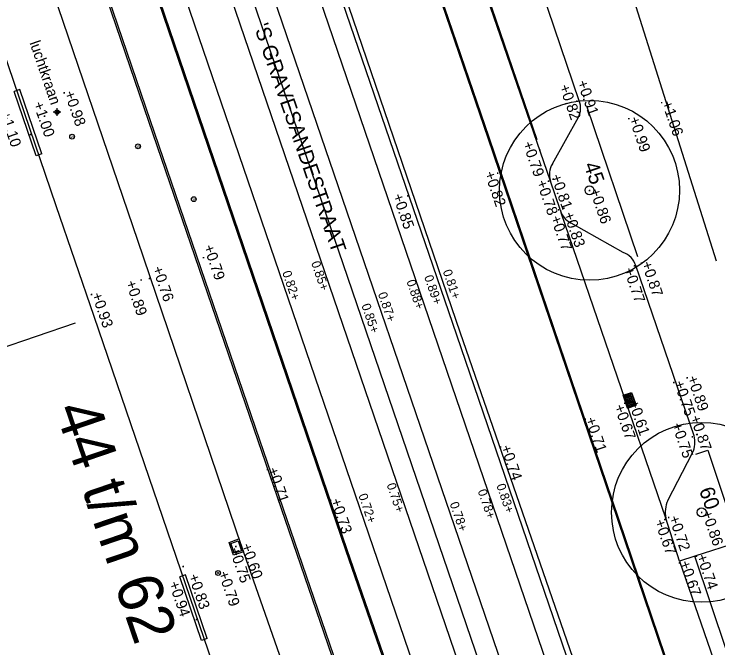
# Model space of a CAD drawing. Extents: x 122462 to 123306, y 485548 to 486417.
# Drawn here: x 122852.27 to 122875.74, y 486006.21 to 486027.34 of the extents above; entities that cross this region are included whole.
import ezdxf

# ---------------------------------------------------------------- set-up
doc = ezdxf.new("R2010")
doc.units = 0
for name, color, linetype in [('B-WE-GR-BOOM-S', 7, 'Continuous'), ('B-WE-GR-BOOM_BOOMDIAMETER-T25', 7, 'Continuous'), ('B-WE-IE-MEUBILAIR_WEGMEUBILAIR-S', 7, 'Continuous'), ('B-WE-OG-BEBOUWING_ROOSTER-G', 7, 'Continuous'), ('B-WE-OG-HOOGTEPUNT-S', 7, 'Continuous'), ('B-WE-OG-PASPUNT_ALGEMEEN-S', 7, 'Continuous'), ('B-WE-OG-TOPOGRAFIE_STRAATNAAM', 7, 'Continuous'), ('B-WE-OG-TOPOKAART-G', 7, 'Continuous'), ('B-WE-RI-HWA_KOLK-S', 7, 'Continuous'), ('B-WE-VH-KANTOPSLUITING_ELEMENT_INRIT-G', 7, 'Continuous'), ('B-WE-VH-KANTOPSLUITING_OPSLUITBAND_100X200-G', 7, 'Continuous'), ('B-WE-VH-KANTOPSLUITING_TROTTOIRBAND_130 150-G', 7, 'Continuous'), ('B-WE-VH-MATERIAALGRENS_ASFALT-G', 7, 'Continuous'), ('B-WE-VW-MARKERING_LANGS_STREEP_11_010-G', 7, 'Continuous'), ('B-WE-ZZ-T18', 7, 'Continuous'), ('Bestaand Hoogtemaat vast', 7, 'Continuous'), ('Level 22', 7, 'Continuous'), ('Level 4', 7, 'Continuous'), ('Level 58', 7, 'Continuous'), ('V markering 1-1 10 cm', 7, 'Continuous'), ('V markering ononderbroken streep 10 cm', 7, 'Continuous'), ('V materiaalscheiding algemeen', 7, 'Continuous'), ('V Rails', 7, 'Continuous'), ('V riool trottoirkolk', 7, 'Continuous'), ('V RWS-band 115-225x250 mm specie', 7, 'Continuous'), ('V trottoirband 180-200x250 mm specie', 7, 'Continuous')]:
    doc.layers.add(name, color=color, linetype=linetype)

msp = doc.modelspace()

# ---------------------------------------------------------------- linework, layer by layer
at = {"layer": 'B-WE-GR-BOOM-S'}
for centre, radius in [((122871.456, 486021.467), 3), ((122871.456, 486021.467), 0.15), ((122871.456, 486021.467), 0.15), ((122875.191, 486010.727), 3), ((122875.191, 486010.727), 0.15), ((122875.191, 486010.727), 0.15)]:
    msp.add_circle(centre, radius, dxfattribs=at)
at = {"layer": 'B-WE-IE-MEUBILAIR_WEGMEUBILAIR-S'}
for centre in [(122854.207, 486023.256), (122856.406, 486022.933), (122858.264, 486021.172), (122859.075, 486008.705)]:
    msp.add_circle(centre, 0.08, dxfattribs=at)
at = {"layer": 'B-WE-OG-BEBOUWING_ROOSTER-G'}
for p, q in [((122852.466, 486024.824), (122852.277, 486024.759)), ((122853.195, 486022.687), (122852.466, 486024.824)), ((122853.006, 486022.622), (122852.277, 486024.759)), ((122853.195, 486022.687), (122853.006, 486022.622)), ((122857.991, 486008.642), (122857.802, 486008.578)), ((122858.715, 486006.52), (122857.991, 486008.642)), ((122858.526, 486006.456), (122857.802, 486008.578)), ((122858.715, 486006.52), (122858.526, 486006.456))]:
    msp.add_line(p, q, dxfattribs=at)
at = {"layer": 'B-WE-OG-HOOGTEPUNT-S'}
for p, q in [((122853.922, 486024.719), (122853.962, 486024.719)), ((122853.942, 486024.739), (122853.942, 486024.699)), ((122871.249, 486024.593), (122871.289, 486024.593)), ((122871.269, 486024.613), (122871.269, 486024.573)), ((122871.009, 486024.437), (122871.049, 486024.437)), ((122871.029, 486024.457), (122871.029, 486024.417)), ((122873.841, 486024.39), (122873.881, 486024.39)), ((122873.861, 486024.41), (122873.861, 486024.37)), ((122853.267, 486023.941), (122853.307, 486023.941)), ((122853.287, 486023.961), (122853.287, 486023.921)), ((122872.765, 486023.878), (122872.765, 486023.838)), ((122872.745, 486023.858), (122872.785, 486023.858)), ((122852.804, 486023.328), (122852.844, 486023.328)), ((122852.824, 486023.348), (122852.824, 486023.308)), ((122869.783, 486022.807), (122869.823, 486022.807)), ((122869.803, 486022.827), (122869.803, 486022.787)), ((122868.374, 486022.038), (122868.414, 486022.038)), ((122868.394, 486022.058), (122868.394, 486022.018)), ((122870.072, 486021.777), (122870.112, 486021.777)), ((122870.092, 486021.797), (122870.092, 486021.757)), ((122870.22, 486021.843), (122870.26, 486021.843)), ((122870.24, 486021.863), (122870.24, 486021.823)), ((122865.381, 486021.288), (122865.421, 486021.288)), ((122865.401, 486021.308), (122865.401, 486021.268)), ((122871.438, 486021.464), (122871.478, 486021.464)), ((122871.458, 486021.484), (122871.458, 486021.444)), ((122870.428, 486020.833), (122870.428, 486020.793)), ((122870.581, 486020.872), (122870.621, 486020.872)), ((122870.601, 486020.892), (122870.601, 486020.852)), ((122870.408, 486020.813), (122870.448, 486020.813)), ((122858.564, 486019.221), (122858.604, 486019.221)), ((122858.584, 486019.241), (122858.584, 486019.201)), ((122872.933, 486018.951), (122872.973, 486018.951)), ((122872.953, 486018.971), (122872.953, 486018.931)), ((122873.163, 486019.035), (122873.203, 486019.035)), ((122873.183, 486019.055), (122873.183, 486019.015)), ((122856.486, 486018.476), (122856.526, 486018.476)), ((122856.506, 486018.496), (122856.506, 486018.456)), ((122856.763, 486018.523), (122856.803, 486018.523)), ((122856.783, 486018.543), (122856.783, 486018.503)), ((122854.853, 486018.015), (122854.853, 486017.975)), ((122854.833, 486017.995), (122854.873, 486017.995)), ((122874.688, 486015.217), (122874.728, 486015.217)), ((122874.708, 486015.237), (122874.708, 486015.197)), ((122874.243, 486015.055), (122874.283, 486015.055)), ((122874.263, 486015.075), (122874.263, 486015.035)), ((122872.793, 486014.486), (122872.793, 486014.446)), ((122872.61, 486014.365), (122872.65, 486014.365)), ((122872.63, 486014.385), (122872.63, 486014.345)), ((122872.773, 486014.466), (122872.813, 486014.466)), ((122871.293, 486013.838), (122871.333, 486013.838)), ((122871.313, 486013.858), (122871.313, 486013.818)), ((122875.026, 486013.325), (122875.066, 486013.325)), ((122875.046, 486013.345), (122875.046, 486013.305)), ((122874.864, 486013.242), (122874.904, 486013.242)), ((122874.884, 486013.262), (122874.884, 486013.222)), ((122868.469, 486012.908), (122868.509, 486012.908)), ((122868.489, 486012.928), (122868.489, 486012.888)), ((122860.697, 486012.16), (122860.737, 486012.16)), ((122860.717, 486012.18), (122860.717, 486012.14)), ((122862.801, 486011.129), (122862.841, 486011.129)), ((122862.821, 486011.149), (122862.821, 486011.109)), ((122875.193, 486010.744), (122875.193, 486010.704)), ((122873.969, 486010.505), (122873.969, 486010.465)), ((122874.073, 486010.555), (122874.113, 486010.555)), ((122874.093, 486010.575), (122874.093, 486010.535)), ((122875.173, 486010.724), (122875.213, 486010.724)), ((122873.949, 486010.485), (122873.989, 486010.485)), ((122859.641, 486009.589), (122859.681, 486009.589)), ((122859.661, 486009.609), (122859.661, 486009.569)), ((122859.821, 486009.625), (122859.861, 486009.625)), ((122859.841, 486009.645), (122859.841, 486009.605)), ((122874.998, 486009.27), (122875.038, 486009.27)), ((122875.018, 486009.29), (122875.018, 486009.25)), ((122857.886, 486008.919), (122857.926, 486008.919)), ((122857.906, 486008.939), (122857.906, 486008.899)), ((122874.436, 486009.048), (122874.476, 486009.048)), ((122874.456, 486009.068), (122874.456, 486009.028)), ((122859.055, 486008.705), (122859.095, 486008.705)), ((122859.075, 486008.725), (122859.075, 486008.685)), ((122858.336, 486007.154), (122858.376, 486007.154)), ((122858.356, 486007.174), (122858.356, 486007.134))]:
    msp.add_line(p, q, dxfattribs=at)
at = {"layer": 'B-WE-OG-PASPUNT_ALGEMEEN-S'}
for p, q in [((122853.708, 486024.076), (122853.708, 486024.204)), ((122853.708, 486024.076), (122853.58, 486024.076)), ((122853.708, 486023.948), (122853.708, 486024.076)), ((122853.836, 486024.076), (122853.708, 486024.076))]:
    msp.add_line(p, q, dxfattribs=at)
for radius in [0.0731, 0.033]:
    msp.add_circle((122853.708, 486024.076), radius, dxfattribs=at)
at = {"layer": 'B-WE-OG-TOPOKAART-G'}
msp.add_line((122860.981, 485999.574), (122854.941, 486017.262), dxfattribs=at)
msp.add_lwpolyline([(122854.941, 486017.262), (122853.681, 486020.951), (122848.906, 486034.937)], dxfattribs=at)
at = {"layer": 'B-WE-RI-HWA_KOLK-S'}
for p, q in [((122872.577, 486014.63), (122872.861, 486014.727)), ((122872.861, 486014.727), (122873.007, 486014.301)), ((122872.723, 486014.204), (122872.577, 486014.63)), ((122872.596, 486014.621), (122872.852, 486014.708)), ((122872.732, 486014.223), (122872.596, 486014.621)), ((122872.852, 486014.708), (122872.988, 486014.311)), ((122872.723, 486014.204), (122873.007, 486014.301)), ((122872.732, 486014.223), (122872.988, 486014.311))]:
    msp.add_line(p, q, dxfattribs=at)
for points in [[(122872.637, 486014.604), (122872.641, 486014.592)], [(122872.817, 486014.676), (122872.643, 486014.617)], [(122872.653, 486014.586), (122872.828, 486014.646)], [(122872.653, 486014.556), (122872.657, 486014.545)], [(122872.834, 486014.629), (122872.659, 486014.569)], [(122872.669, 486014.509), (122872.673, 486014.498)], [(122872.67, 486014.539), (122872.844, 486014.599)], [(122872.85, 486014.582), (122872.676, 486014.522)], [(122872.686, 486014.492), (122872.86, 486014.551)], [(122872.866, 486014.534), (122872.692, 486014.475)], [(122872.702, 486014.444), (122872.876, 486014.504)], [(122872.882, 486014.487), (122872.708, 486014.427)], [(122872.834, 486014.659), (122872.83, 486014.67)], [(122872.85, 486014.611), (122872.846, 486014.623)], [(122872.866, 486014.564), (122872.863, 486014.575)], [(122872.883, 486014.517), (122872.879, 486014.528)], [(122872.899, 486014.469), (122872.895, 486014.481)], [(122872.685, 486014.462), (122872.689, 486014.451)], [(122872.702, 486014.415), (122872.706, 486014.403)], [(122872.718, 486014.397), (122872.893, 486014.457)], [(122872.718, 486014.367), (122872.722, 486014.356)], [(122872.898, 486014.44), (122872.724, 486014.38)], [(122872.734, 486014.35), (122872.909, 486014.409)], [(122872.734, 486014.32), (122872.738, 486014.309)], [(122872.915, 486014.392), (122872.74, 486014.333)], [(122872.75, 486014.273), (122872.754, 486014.261)], [(122872.751, 486014.302), (122872.925, 486014.362)], [(122872.931, 486014.345), (122872.757, 486014.285)], [(122872.767, 486014.255), (122872.941, 486014.315)], [(122872.915, 486014.422), (122872.911, 486014.433)], [(122872.931, 486014.375), (122872.927, 486014.386)], [(122872.947, 486014.327), (122872.944, 486014.339)]]:
    msp.add_lwpolyline(points, dxfattribs=at)
for centre, start, end in [((122872.646, 486014.607), 108.9043, 198.9043), ((122872.65, 486014.596), 198.9043, 288.9043), ((122872.663, 486014.56), 108.9043, 198.9043), ((122872.666, 486014.548), 198.9043, 288.9043), ((122872.679, 486014.512), 108.9043, 198.9043), ((122872.683, 486014.501), 198.9043, 288.9043), ((122872.821, 486014.667), 18.9043, 108.9043), ((122872.825, 486014.655), 288.9043, 18.9043), ((122872.837, 486014.619), 18.9043, 108.9043), ((122872.841, 486014.608), 288.9043, 18.9043), ((122872.853, 486014.572), 18.9043, 108.9043), ((122872.857, 486014.561), 288.9043, 18.9043), ((122872.869, 486014.525), 18.9043, 108.9043), ((122872.873, 486014.513), 288.9043, 18.9043), ((122872.885, 486014.478), 18.9043, 108.9043), ((122872.695, 486014.465), 108.9043, 198.9043), ((122872.699, 486014.454), 198.9043, 288.9043), ((122872.711, 486014.418), 108.9043, 198.9043), ((122872.715, 486014.406), 198.9043, 288.9043), ((122872.727, 486014.37), 108.9043, 198.9043), ((122872.731, 486014.359), 198.9043, 288.9043), ((122872.744, 486014.323), 108.9043, 198.9043), ((122872.747, 486014.312), 198.9043, 288.9043), ((122872.76, 486014.276), 108.9043, 198.9043), ((122872.764, 486014.265), 198.9043, 288.9043), ((122872.889, 486014.466), 288.9043, 18.9043), ((122872.902, 486014.43), 18.9043, 108.9043), ((122872.906, 486014.419), 288.9043, 18.9043), ((122872.918, 486014.383), 18.9043, 108.9043), ((122872.922, 486014.372), 288.9043, 18.9043), ((122872.934, 486014.336), 18.9043, 108.9043), ((122872.938, 486014.324), 288.9043, 18.9043)]:
    msp.add_arc(centre, 0.01, start, end, dxfattribs=at)
at = {"layer": 'B-WE-VH-KANTOPSLUITING_ELEMENT_INRIT-G'}
msp.add_lwpolyline([(122876.1, 486004.342), (122876.567, 486004.501), (122874.962, 486009.263), (122874.461, 486009.099)], close=True, dxfattribs=at)
at = {"layer": 'B-WE-VH-KANTOPSLUITING_OPSLUITBAND_100X200-G'}
msp.add_line((122871.36, 486024.279), (122873.059, 486019.257), dxfattribs=at)
msp.add_lwpolyline([(122875.003, 486012.672), (122875.403, 486012.797), (122876.421, 486009.733), (122874.962, 486009.263)], dxfattribs=at)
at = {"layer": 'B-WE-VH-KANTOPSLUITING_TROTTOIRBAND_130 150-G'}
msp.add_line((122874.461, 486009.099), (122873.998, 486010.535), dxfattribs=at)
for points in [[(122871.112, 486024.447), (122869.664, 486028.716)], [(122870.22, 486022.347), (122871.085, 486023.901)], [(122870.474, 486020.826), (122870.152, 486021.777)], [(122872.577, 486019.394), (122870.84, 486020.375)], [(122874.942, 486013.282), (122872.999, 486018.955)], [(122874.062, 486011.124), (122874.892, 486012.707)]]:
    msp.add_lwpolyline(points, dxfattribs=at)
for centre, radius, start, end in [((122870.516, 486024.203), 0.644, 332.0526, 22.274), ((122870.788, 486021.99), 0.671, 147.8548, 198.5105), ((122871.137, 486020.99), 0.683, 193.9744, 244.2077), ((122872.362, 486018.764), 0.665, 16.6992, 71.1589), ((122874.079, 486013.068), 0.889, 336.0879, 13.9552), ((122875.015, 486010.722), 1.034, 157.1414, 190.4477)]:
    msp.add_arc(centre, radius, start, end, dxfattribs=at)
at = {"layer": 'B-WE-VH-MATERIAALGRENS_ASFALT-G'}
for p, q in [((122870.152, 486021.777), (122867.145, 486030.539)), ((122873.998, 486010.535), (122870.512, 486020.715))]:
    msp.add_line(p, q, dxfattribs=at)
at = {"layer": 'B-WE-VW-MARKERING_LANGS_STREEP_11_010-G'}
msp.add_lwpolyline([(122869.714, 486023.153), (122867.665, 486029.129)], dxfattribs=at)
at = {"layer": 'Level 22'}
msp.add_lwpolyline([(122868.721, 486040.257), (122871.2, 486033.479), (122872.44, 486029.379), (122872.864, 486028.033), (122875.673, 486019.114)], dxfattribs=at)
at = {"layer": 'Level 4'}
msp.add_line((122844.648, 486013.747), (122854.324, 486017.051), dxfattribs=at)
at = {"layer": 'V markering 1-1 10 cm'}
for points in [[(122861.268, 486043.255), (122864.477, 486033.82), (122868.105, 486023.234), (122872.215, 486011.133), (122877.675, 485994.999), (122880.312, 485987.313), (122885.038, 485973.513), (122892.674, 485951.631), (122899.173, 485932.732), (122905.905, 485913.305)], [(122897.69, 485909.552), (122896.019, 485914.579), (122892.466, 485924.842), (122886.539, 485941.858), (122880.87, 485958.414), (122875.603, 485973.852), (122873.11, 485981.1), (122869.222, 485992.577), (122863.38, 486009.478), (122855.336, 486033.09), (122853.219, 486039.33)], [(122869.601, 485986.295), (122864.164, 486002.161), (122860.412, 486013.116), (122856.761, 486023.765), (122852.874, 486035.171)]]:
    msp.add_lwpolyline(points, dxfattribs=at)
at = {"layer": 'V markering ononderbroken streep 10 cm'}
msp.add_line((122874.406, 485986.361), (122855.755, 486040.94), dxfattribs=at)
msp.add_lwpolyline([(122878.319, 485984.197), (122872.773, 486000.466), (122867.161, 486016.698), (122860.607, 486035.872), (122857.454, 486044.963)], dxfattribs=at)
at = {"layer": 'V materiaalscheiding algemeen'}
for points in [[(122897.072, 485911.4), (122895.975, 485914.564), (122892.423, 485924.827), (122886.495, 485941.843), (122880.827, 485958.399), (122875.559, 485973.837), (122873.066, 485981.085), (122869.178, 485992.562), (122863.337, 486009.463), (122855.292, 486033.075), (122851.509, 486044.226)], [(122861.232, 486043.247), (122864.442, 486033.808), (122868.07, 486023.222), (122872.18, 486011.121), (122877.64, 485994.987), (122880.277, 485987.301), (122885.003, 485973.501), (122892.639, 485951.618), (122899.138, 485932.72), (122905.87, 485913.293)], [(122869.833, 485985.807), (122864.223, 486002.181), (122860.47, 486013.137), (122856.82, 486023.786), (122852.933, 486035.191), (122852.304, 486036.83)]]:
    msp.add_lwpolyline(points, dxfattribs=at)
at = {"layer": 'V Rails'}
for p, q in [((122859.04, 486037.86), (122898.563, 485922.205)), ((122857.682, 486037.396), (122897.205, 485921.741)), ((122856.774, 486035.862), (122895.923, 485921.303)), ((122855.416, 486035.398), (122894.565, 485920.838))]:
    msp.add_line(p, q, dxfattribs=at)
at = {"layer": 'V riool trottoirkolk'}
for p, q in [((122859.44, 486009.723), (122859.77, 486009.838)), ((122859.77, 486009.838), (122859.919, 486009.413)), ((122859.787, 486009.791), (122859.782, 486009.789)), ((122859.588, 486009.298), (122859.44, 486009.723)), ((122859.776, 486009.777), (122859.791, 486009.732)), ((122859.791, 486009.732), (122859.802, 486009.701)), ((122859.82, 486009.697), (122859.815, 486009.695)), ((122859.817, 486009.659), (122859.843, 486009.583)), ((122859.828, 486009.673), (122859.823, 486009.671)), ((122859.861, 486009.579), (122859.856, 486009.577)), ((122859.869, 486009.555), (122859.864, 486009.553)), ((122859.919, 486009.413), (122859.588, 486009.298)), ((122859.858, 486009.541), (122859.885, 486009.465)), ((122859.902, 486009.461), (122859.897, 486009.459))]:
    msp.add_line(p, q, dxfattribs=at)
msp.add_lwpolyline([(122859.619, 486009.362), (122859.503, 486009.692), (122859.74, 486009.775), (122859.855, 486009.444)], close=True, dxfattribs=at)
for centre, start, end in [((122859.785, 486009.78), 109.2454, 199.2454), ((122859.812, 486009.704), 199.2454, 289.2454), ((122859.826, 486009.662), 109.2454, 199.2454), ((122859.853, 486009.586), 199.2454, 289.2454), ((122859.868, 486009.544), 109.2454, 199.2454), ((122859.894, 486009.468), 199.2454, 289.2454)]:
    msp.add_arc(centre, 0.01, start, end, dxfattribs=at)
at = {"layer": 'V RWS-band 115-225x250 mm specie'}
msp.add_lwpolyline([(122856.63, 486046.061), (122856.864, 486046.126), (122860.451, 486035.813), (122867.025, 486016.652), (122872.586, 486000.358), (122878.14, 485984.014)], dxfattribs=at)
at = {"layer": 'V trottoirband 180-200x250 mm specie'}
msp.add_lwpolyline([(122852.481, 486031.173), (122852.776, 486030.329), (122853.248, 486029.041), (122856.391, 486019.807), (122859.841, 486009.625), (122862.795, 486001.163), (122864.85, 485995.031), (122866.797, 485989.319), (122867.519, 485987.249)], dxfattribs=at)

# ---------------------------------------------------------------- texts
at = {"layer": 'B-WE-GR-BOOM_BOOMDIAMETER-T25'}
for s, rotation, p in [('45', 289, (122871.261, 486022.317)), ('60', 289.2634, (122875.102, 486011.471))]:
    msp.add_text(s, height=0.5, rotation=rotation, dxfattribs=at).set_placement(p)
at = {"layer": 'B-WE-IE-MEUBILAIR_WEGMEUBILAIR-S'}
for p in [(122854.165, 486023.214), (122856.364, 486022.891), (122858.221, 486021.13), (122859.033, 486008.663)]:
    msp.add_text('W', height=0.08, dxfattribs=at).set_placement(p)
at = {"layer": 'B-WE-OG-HOOGTEPUNT-S'}
for s, rotation, p in [('+0.91', 289.2634, (122871.038, 486025.071)), ('+0.82', 289.2634, (122870.442, 486024.928)), ('+0.98', 289, (122853.942, 486024.719)), ('+1.00', 289, (122852.907, 486024.358)), ('+1.06', 289, (122873.861, 486024.39)), ('+1.10', 289, (122851.792, 486024.027)), ('+0.99', 289, (122872.765, 486023.858)), ('+0.79', 289.2634, (122869.221, 486023.032)), ('+0.82', 289, (122867.947, 486022.038)), ('+0.78', 289.2634, (122869.679, 486021.745)), ('+0.81', 289.2634, (122870.162, 486021.937)), ('+0.85', 289, (122864.889, 486021.288)), ('+0.86', 289, (122871.458, 486021.464)), ('+0.77', 289.2634, (122870.148, 486020.557)), ('+0.83', 289.2634, (122870.586, 486020.68)), ('+0.79', 289, (122858.584, 486019.588)), ('+0.87', 289, (122873.183, 486019.035)), ('+0.76', 289, (122856.879, 486018.87)), ('+0.77', 289, (122872.589, 486018.827)), ('+0.89', 289, (122855.986, 486018.399)), ('+0.93', 289, (122854.853, 486017.995)), ('+0.89', 289, (122874.708, 486015.217)), ('+0.75', 289, (122874.263, 486015.055)), ('+0.67', 289.2634, (122872.27, 486014.263)), ('+0.61', 289, (122872.745, 486014.407)), ('+0.71', 289, (122871.313, 486013.838)), ('+0.87', 289, (122874.804, 486013.897)), ('+0.75', 289, (122874.194, 486013.65)), ('+0.74', 289, (122868.489, 486012.908)), ('+0.71', 289, (122860.717, 486012.16)), ('+0.73', 289, (122862.821, 486011.129)), ('+0.86', 289, (122875.193, 486010.724)), ('+0.72', 289, (122874.093, 486010.555)), ('+0.67', 289.2634, (122873.619, 486010.426)), ('+0.60', 289, (122859.841, 486009.625)), ('+0.75', 289, (122859.443, 486009.489)), ('+0.67', 289, (122874.456, 486009.048)), ('+0.74', 289, (122875.018, 486009.27)), ('+0.83', 289, (122858.077, 486008.61)), ('+0.79', 289, (122859.075, 486008.705)), ('+0.94', 289, (122857.425, 486008.364))]:
    msp.add_text(s, height=0.36, rotation=rotation, dxfattribs=at).set_placement(p)
at = {"layer": 'B-WE-OG-TOPOGRAFIE_STRAATNAAM'}
msp.add_text("'S GRAVESANDESTRAAT", height=0.5, rotation=289.0841, dxfattribs=at).set_placement((122860.259, 486026.936))
at = {"layer": 'B-WE-ZZ-T18'}
msp.add_text('luchtkraan', height=0.36, rotation=289, dxfattribs=at).set_placement((122852.785, 486026.387))
at = {"layer": 'Bestaand Hoogtemaat vast'}
for s, p in [('0.85+', (122862.172, 486019.051)), ('0.82+', (122861.207, 486018.729)), ('0.81+', (122866.561, 486018.767)), ('0.88+', (122865.35, 486018.43)), ('0.89+', (122865.939, 486018.583)), ('0.87+', (122864.399, 486018.015)), ('0.85+', (122863.849, 486017.632)), ('0.75+', (122864.689, 486011.649)), ('0.83+', (122868.347, 486011.627)), ('0.78+', (122867.726, 486011.442)), ('0.72+', (122863.748, 486011.297)), ('0.78+', (122866.792, 486011.02))]:
    msp.add_text(s, height=0.3, rotation=288.8803, dxfattribs=at).set_placement(p)
at = {"layer": 'Level 58'}
msp.add_text('44 t/m 62', height=1.5, rotation=288.8526, dxfattribs=at).set_placement((122853.623, 486014.162))

doc.saveas('drawing.dxf')
